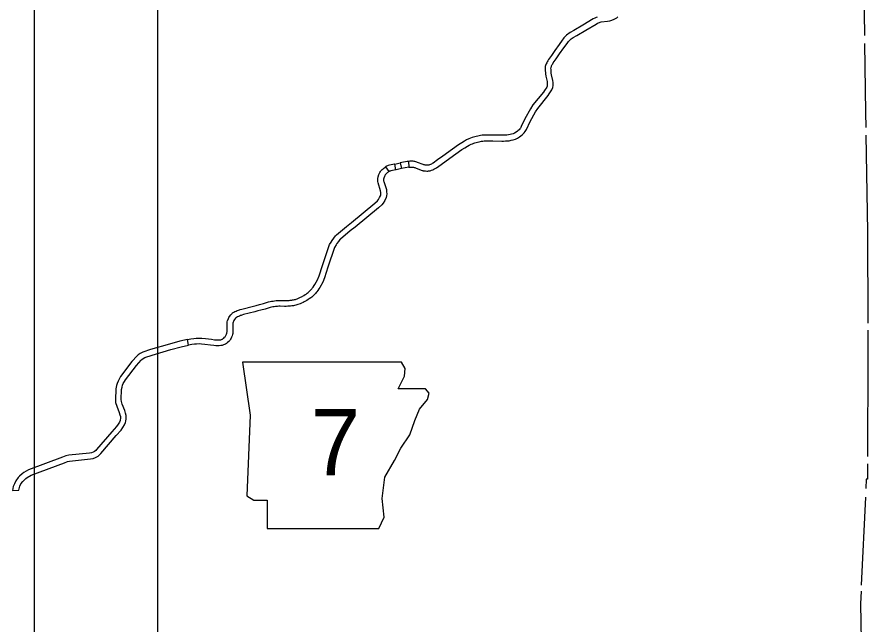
# Model space of a CAD drawing. Extents: x 77230 to 630905, y 790554 to 1662844.
# Drawn here: x 585543 to 622128, y 1577441 to 1603582 of the extents above; entities that cross this region are included whole.
import ezdxf

# ---------------------------------------------------------------- set-up
doc = ezdxf.new("R2010")
doc.units = 0
for name, color, linetype in [('Level 10', 7, 'Continuous'), ('Level 24', 7, 'Continuous'), ('Level 28', 7, 'Continuous'), ('Level 43', 7, 'Continuous')]:
    doc.layers.add(name, color=color, linetype=linetype)

msp = doc.modelspace()

# ---------------------------------------------------------------- linework, layer by layer
at = {"layer": 'Level 10'}
for points in [[(610490, 1603582), (610441, 1603562), (610391, 1603539), (610315, 1603498), (609866, 1603232), (609482, 1603000), (609322, 1602911), (609265, 1602874), (609219, 1602841), (609172, 1602804), (609110, 1602744), (609058, 1602685), (609022, 1602640), (608987, 1602590), (608849, 1602400), (608666, 1602138), (608518, 1601926), (608394, 1601749), (608363, 1601703), (608334, 1601652), (608316, 1601616), (608298, 1601576), (608284, 1601540), (608269, 1601502), (608256, 1601451), (608250, 1601395), (608252, 1601324)], [(610578, 1603348), (610608, 1603358), (610655, 1603370), (610923, 1603399), (611033, 1603422), (611112, 1603444), (611221, 1603484), (611331, 1603548), (611378, 1603583)], [(608501, 1601330), (608500, 1601385), (608502, 1601406), (608507, 1601425), (608517, 1601449), (608528, 1601478), (608542, 1601509), (608555, 1601536), (608575, 1601570), (608600, 1601608), (608723, 1601783), (608871, 1601995), (609053, 1602255), (609190, 1602445), (609222, 1602490), (609250, 1602525), (609290, 1602571), (609337, 1602615), (609369, 1602641), (609405, 1602667), (609451, 1602696), (609608, 1602784), (609994, 1603017), (610439, 1603280), (610503, 1603316), (610540, 1603333), (610578, 1603348)], [(608252, 1601324), (608260, 1601142), (608280, 1601038), (608336, 1600808), (608342, 1600756), (608340, 1600659), (608333, 1600611), (608315, 1600566), (608221, 1600417), (608174, 1600355), (607725, 1599801), (607621, 1599636), (607381, 1599207)], [(607604, 1599092), (607836, 1599508), (607929, 1599655), (608372, 1600202), (608427, 1600275), (608539, 1600452), (608576, 1600546), (608590, 1600638), (608592, 1600768), (608583, 1600851), (608525, 1601091), (608509, 1601172), (608501, 1601330)], [(607381, 1599207), (607222, 1598868), (607202, 1598834), (607182, 1598802), (607157, 1598771), (607125, 1598736), (607095, 1598704), (607058, 1598675), (607002, 1598637), (606935, 1598595), (606872, 1598565), (606802, 1598540), (606739, 1598525), (606673, 1598514), (606600, 1598508), (606530, 1598503), (606459, 1598500), (606385, 1598500), (605997, 1598503), (605790, 1598503), (605613, 1598505), (605538, 1598497), (605463, 1598485), (605353, 1598461), (605284, 1598444), (605222, 1598427), (605161, 1598410), (605111, 1598395), (605037, 1598369), (604966, 1598341), (604870, 1598298), (604780, 1598247), (604660, 1598172), (604529, 1598086), (604267, 1597903), (603846, 1597604), (603625, 1597448), (603431, 1597305), (603414, 1597293), (603392, 1597280), (603357, 1597262), (603318, 1597243), (603272, 1597225), (603254, 1597218), (603241, 1597214), (603238, 1597213), (603223, 1597212), (603201, 1597211), (603165, 1597211), (603123, 1597213), (603087, 1597215), (603056, 1597220), (603044, 1597223), (603031, 1597227), (603001, 1597237), (602766, 1597328), (602729, 1597341), (602692, 1597354), (602653, 1597365), (602611, 1597373), (602581, 1597377), (602553, 1597380), (602516, 1597382), (602473, 1597382), (602434, 1597381), (602375, 1597376), (602383, 1597126)], [(602383, 1597126), (602415, 1597129), (602446, 1597131), (602476, 1597132), (602510, 1597132), (602533, 1597130), (602552, 1597128), (602571, 1597126), (602595, 1597121), (602620, 1597114), (602648, 1597105), (602678, 1597094), (602915, 1597002), (602957, 1596988), (602984, 1596980), (603010, 1596975), (603057, 1596967), (603109, 1596963), (603161, 1596961), (603205, 1596961), (603240, 1596962), (603272, 1596966), (603298, 1596970), (603339, 1596982), (603367, 1596994), (603416, 1597013), (603468, 1597037), (603516, 1597063), (603548, 1597082), (603575, 1597100), (603771, 1597245), (603990, 1597400), (604411, 1597698), (604670, 1597879), (604795, 1597961), (604908, 1598032), (604983, 1598075), (605062, 1598110), (605124, 1598134), (605189, 1598157), (605232, 1598171), (605288, 1598186), (605346, 1598202), (605409, 1598217), (605510, 1598239), (605571, 1598249), (605625, 1598255), (605788, 1598253), (605996, 1598253), (606384, 1598250), (606465, 1598250), (606544, 1598253), (606619, 1598258), (606704, 1598265), (606790, 1598280), (606873, 1598300), (606968, 1598334), (607055, 1598375), (607139, 1598427), (607207, 1598474), (607264, 1598519), (607308, 1598565), (607347, 1598608), (607387, 1598658), (607415, 1598704), (607443, 1598751), (607604, 1599092)], [(601780, 1597259), (601787, 1597261), (602020, 1597313), (602072, 1597068)], [(602375, 1597376), (602351, 1597373), (602313, 1597368), (602081, 1597326), (602020, 1597313)], [(601070, 1596710), (601103, 1596809), (601125, 1596861), (601147, 1596901), (601169, 1596935), (601189, 1596962), (601215, 1596993), (601241, 1597021), (601281, 1597058), (601316, 1597089), (601350, 1597116), (601379, 1597135), (601529, 1596935)], [(601529, 1596935), (601512, 1596923), (601498, 1596914), (601476, 1596897), (601449, 1596873), (601416, 1596842), (601402, 1596827), (601387, 1596809), (601374, 1596791), (601361, 1596772), (601351, 1596752), (601337, 1596720), (601312, 1596647)], [(601780, 1597259), (601766, 1597256), (601552, 1597207), (601504, 1597193), (601464, 1597179), (601430, 1597164), (601404, 1597150), (601379, 1597135)], [(601828, 1597014), (601614, 1596964), (601581, 1596955), (601558, 1596947), (601540, 1596941), (601529, 1596935)], [(602072, 1597068), (601842, 1597017), (601828, 1597014), (601780, 1597259)], [(602383, 1597126), (602071, 1597071)], [(599048, 1593905), (599088, 1593974), (599159, 1594078), (599240, 1594178), (599278, 1594215), (599710, 1594577), (599921, 1594745), (600925, 1595572), (601043, 1595682), (601081, 1595729), (601133, 1595815), (601171, 1595899), (601180, 1595939), (601186, 1595997), (601185, 1596043), (601177, 1596108), (601067, 1596452), (601055, 1596513), (601056, 1596633), (601070, 1596710)], [(601312, 1596647), (601305, 1596610), (601305, 1596537), (601309, 1596514), (601421, 1596164), (601435, 1596063), (601437, 1595986), (601427, 1595898), (601409, 1595819), (601355, 1595698), (601286, 1595585), (601227, 1595511), (601090, 1595384), (600078, 1594551), (599868, 1594383), (599446, 1594030), (599425, 1594009), (599360, 1593929), (599299, 1593841), (599264, 1593780)], [(598462, 1592287), (598533, 1592460), (598673, 1592899), (598980, 1593796), (599048, 1593905)], [(599264, 1593780), (599196, 1593669), (598912, 1592827), (598769, 1592374), (598689, 1592180)], [(592917, 1589469), (592867, 1589714), (593019, 1589741), (593138, 1589759), (593245, 1589770), (593376, 1589773), (593490, 1589770), (593650, 1589757), (593898, 1589726), (594040, 1589705), (594111, 1589698), (594167, 1589696), (594220, 1589696), (594267, 1589701), (594305, 1589708), (594332, 1589717), (594359, 1589728), (594374, 1589737), (594405, 1589757), (594435, 1589778), (594468, 1589810), (594491, 1589834), (594507, 1589859), (594524, 1589886), (594539, 1589919), (594551, 1589951), (594563, 1589990), (594568, 1590013), (594571, 1590043), (594571, 1590138), (594572, 1590424), (594580, 1590476), (594597, 1590532), (594604, 1590552), (594631, 1590615), (594656, 1590661), (594685, 1590708), (594736, 1590782), (594792, 1590840), (594810, 1590856), (594862, 1590889), (594912, 1590913), (594962, 1590936), (595012, 1590957), (595068, 1590979), (595106, 1590992), (595138, 1591002), (595215, 1591026), (595704, 1591146), (595828, 1591185), (595964, 1591220), (596140, 1591268), (596361, 1591330), (596430, 1591347), (596489, 1591359), (596550, 1591371), (596615, 1591383), (596679, 1591389), (596729, 1591391), (596801, 1591394), (596867, 1591394), (597041, 1591389), (597111, 1591390), (597167, 1591393), (597241, 1591398), (597285, 1591401), (597353, 1591409), (597385, 1591416), (597425, 1591424), (597469, 1591434), (597509, 1591443), (597545, 1591453), (597581, 1591466), (597670, 1591504), (597731, 1591533), (597775, 1591555), (597876, 1591612), (597931, 1591646), (597970, 1591672), (598022, 1591709), (598054, 1591735), (598084, 1591760), (598116, 1591789), (598148, 1591820), (598176, 1591848), (598194, 1591867), (598216, 1591893), (598238, 1591920), (598274, 1591966), (598319, 1592033), (598352, 1592081), (598462, 1592287)], [(598689, 1592180), (598567, 1591951), (598525, 1591891), (598476, 1591819), (598435, 1591766), (598409, 1591734), (598379, 1591698), (598353, 1591672), (598323, 1591641), (598287, 1591607), (598248, 1591572), (598212, 1591542), (598175, 1591512), (598110, 1591465), (598066, 1591436), (598008, 1591400), (597890, 1591333), (597842, 1591309), (597776, 1591277), (597716, 1591250), (597622, 1591215), (597572, 1591201), (597524, 1591190), (597477, 1591179), (597433, 1591170), (597359, 1591157), (597307, 1591152), (597257, 1591148), (597181, 1591143), (597119, 1591140), (597040, 1591139), (596863, 1591144), (596805, 1591144), (596738, 1591141), (596697, 1591140), (596649, 1591135), (596595, 1591126), (596539, 1591114), (596485, 1591103), (596425, 1591088), (596206, 1591027), (596028, 1590979), (595896, 1590945), (595771, 1590906), (595282, 1590785), (595214, 1590764), (595184, 1590754), (595154, 1590744), (595107, 1590725), (595062, 1590706), (595018, 1590687), (594979, 1590667), (594960, 1590655), (594943, 1590639), (594895, 1590573), (594871, 1590534), (594846, 1590485), (594839, 1590468), (594832, 1590448), (594828, 1590435), (594825, 1590425), (594821, 1590395), (594821, 1590140), (594821, 1590028), (594815, 1589973), (594806, 1589929), (594788, 1589870), (594770, 1589822), (594744, 1589768), (594717, 1589724), (594687, 1589678), (594645, 1589634), (594596, 1589587), (594548, 1589551), (594502, 1589522), (594469, 1589504), (594420, 1589483), (594367, 1589465), (594302, 1589453), (594234, 1589447), (594163, 1589445), (594093, 1589449), (594010, 1589457), (593864, 1589478), (593624, 1589508), (593477, 1589521), (593376, 1589523), (593261, 1589521), (593170, 1589511), (593059, 1589494), (592917, 1589469)], [(592867, 1589714), (592545, 1589641), (592095, 1589520), (591281, 1589282), (590947, 1589167), (590840, 1589112), (590758, 1589052), (590706, 1589008), (590486, 1588763), (589999, 1588125), (589944, 1588041), (589885, 1587924), (589846, 1587831), (589817, 1587732), (589790, 1587596), (589776, 1587124), (589784, 1587013), (589828, 1586850), (589941, 1586578)], [(590177, 1586662), (590065, 1586930), (590032, 1587054), (590027, 1587129), (590039, 1587568), (590060, 1587672), (590082, 1587747), (590112, 1587820), (590161, 1587916), (590203, 1587981), (590678, 1588603), (590880, 1588828), (590912, 1588855), (590972, 1588898), (591045, 1588936), (591357, 1589044), (592162, 1589280), (592605, 1589398), (592917, 1589469), (592867, 1589714)], [(589941, 1586578), (589970, 1586480), (589986, 1586406), (589991, 1586357), (589991, 1586320), (589981, 1586258), (589972, 1586228), (589945, 1586163), (589889, 1586070), (589822, 1585977), (589616, 1585748), (588953, 1584984)], [(589142, 1584820), (589803, 1585583), (590017, 1585820), (590097, 1585933), (590168, 1586050), (590208, 1586145), (590225, 1586202), (590241, 1586298), (590241, 1586369), (590233, 1586445), (590213, 1586543), (590177, 1586662)], [(588953, 1584984), (588925, 1584948), (588878, 1584907), (588813, 1584869), (588748, 1584844), (588666, 1584831), (587765, 1584738), (587644, 1584711), (587493, 1584651), (586040, 1584110), (585841, 1583991), (585766, 1583938), (585654, 1583838), (585599, 1583778), (585492, 1583645), (585431, 1583508), (585382, 1583395), (585342, 1583227), (585615, 1583236)], [(585615, 1583236), (585660, 1583407), (585707, 1583513), (585789, 1583615), (585829, 1583659), (585922, 1583742), (585978, 1583781), (586149, 1583884), (587583, 1584417), (587718, 1584471), (587805, 1584491), (588699, 1584583), (588812, 1584602), (588922, 1584642), (589025, 1584704), (589107, 1584775), (589142, 1584820)]]:
    msp.add_lwpolyline(points, dxfattribs=at)
at = {"layer": 'Level 24'}
msp.add_lwpolyline([(595230, 1588742), (595573, 1586458), (595421, 1582994), (595725, 1582804), (596296, 1582804), (596296, 1581586), (601092, 1581586), (601321, 1582081), (601245, 1582880), (601359, 1583794), (601778, 1584517), (602044, 1585050), (602425, 1585621), (602653, 1586230), (602843, 1586725), (603186, 1587143), (603262, 1587410), (603110, 1587600), (601930, 1587600), (602196, 1588133), (602234, 1588476), (602077, 1588739)], close=True, dxfattribs=at)
msp.add_lwpolyline([(595230, 1588742), (595573, 1586458), (595421, 1582994), (595725, 1582804), (596296, 1582804), (596296, 1581586), (601092, 1581586), (601321, 1582081), (601245, 1582880), (601359, 1583794), (601778, 1584517), (602044, 1585050), (602425, 1585621), (602653, 1586230), (602843, 1586725), (603186, 1587143), (603262, 1587410), (603110, 1587600), (601930, 1587600), (602196, 1588133), (602234, 1588476), (602077, 1588739)], close=True, dxfattribs=at)
at = {"layer": 'Level 28'}
for p, q in [((591576, 1662844), (591576, 1483324)), ((586296, 1488604), (586296, 1658884))]:
    msp.add_line(p, q, dxfattribs=at)
at = {"layer": 'Level 43'}
for points in [[(621950, 1604713), (621976, 1602794)], [(621980, 1602438), (622020, 1599475)], [(622020, 1599475), (622030, 1598836)], [(622036, 1598501), (622101, 1594353), (622120, 1590420)], [(622122, 1590123), (622128, 1588926), (622109, 1584686)], [(622108, 1584371), (622105, 1583714), (622052, 1583711), (622033, 1583308)], [(622016, 1582932), (621840, 1579147)], [(621828, 1578890), (621803, 1578347)], [(621803, 1578347), (621841, 1576777)]]:
    msp.add_lwpolyline(points, dxfattribs=at)

# ---------------------------------------------------------------- texts
at = {"layer": 'Level 24'}
msp.add_text('7', height=2851, dxfattribs=at).set_placement((598177, 1583878))
msp.add_text('7', height=2851, dxfattribs=at).set_placement((598177, 1583878))

doc.saveas('drawing.dxf')
